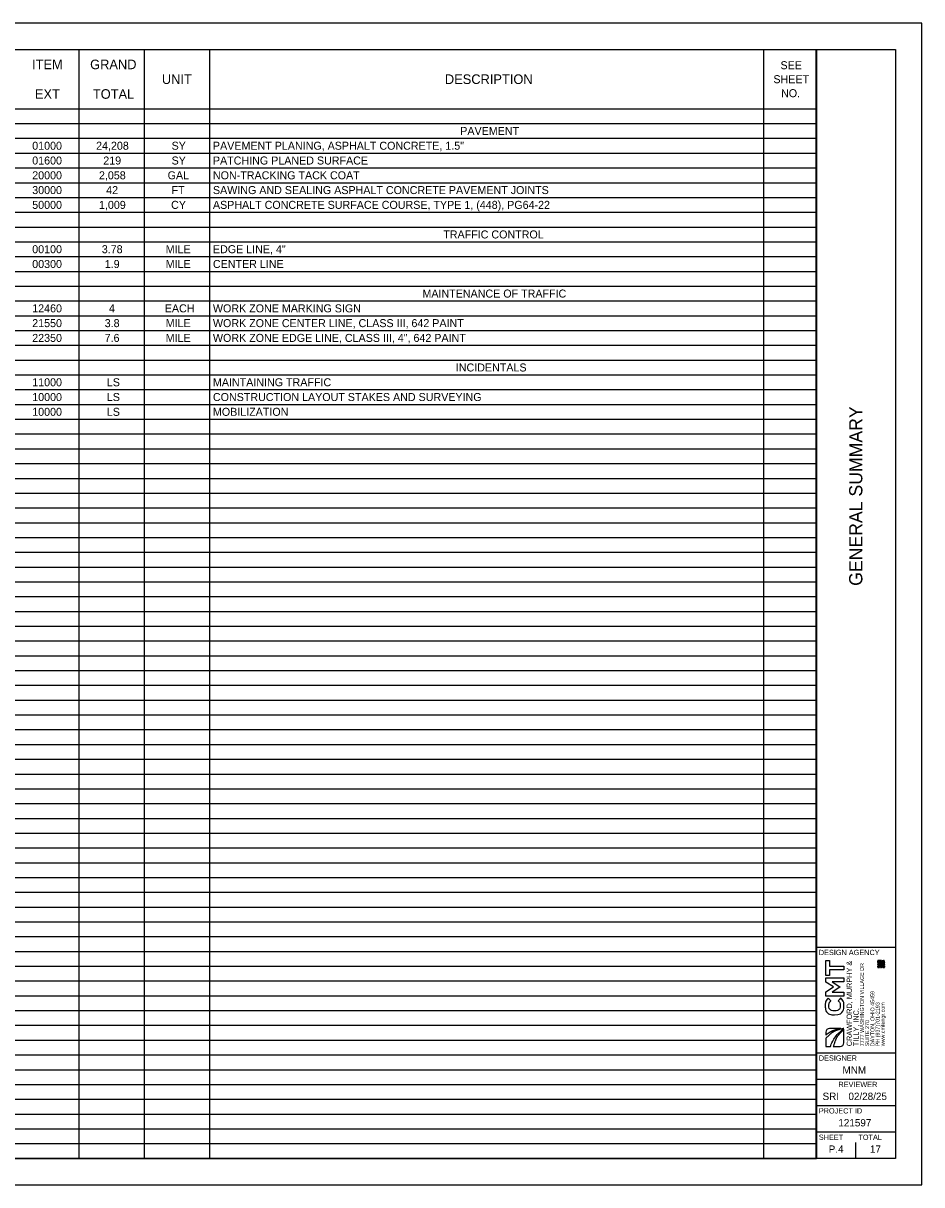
# Model space of a CAD drawing. Extents: x 0 to 34, y 0 to 22.
# Drawn here: x 16.98 to 34, y 0 to 22 of the extents above; entities that cross this region are included whole.
import ezdxf

# ---------------------------------------------------------------- set-up
doc = ezdxf.new("R2010")
doc.units = 0
for name, color, linetype in [('Common-Title block info', 7, 'Continuous'), ('LOGOS', 7, 'Continuous'), ('SH_Border', 7, 'Continuous'), ('SH_Cut_Line', 7, 'Continuous'), ('SH_Data', 7, 'Continuous'), ('SH_Text', 7, 'Continuous')]:
    doc.layers.add(name, color=color, linetype=linetype)

msp = doc.modelspace()

# ---------------------------------------------------------------- linework, layer by layer
at = {"layer": 'Common-Title block info'}
for p, q in [((32.184, 2.889), (32.184, 2.838)), ((32.47, 2.96), (32.254, 2.96)), ((32.525, 2.96), (32.525, 2.96)), ((32.526, 2.688), (32.526, 2.941)), ((32.184, 2.773), (32.184, 2.618)), ((32.184, 2.618), (32.267, 2.618)), ((32.324, 2.618), (32.455, 2.618))]:
    msp.add_line(p, q, dxfattribs=at)
msp.add_lwpolyline([(32.526, 2.941), (32.526, 2.941)], dxfattribs=at)
for centre, start, end in [((32.254, 2.889), 90, 180), ((32.455, 2.688), 270, 360)]:
    msp.add_arc(centre, 0.0708, start, end, dxfattribs=at)
for points, degree in [([(32.525, 2.96), (32.393, 2.934), (32.272, 2.867), (32.184, 2.773)], 2), ([(32.184, 2.838), (32.266, 2.9), (32.365, 2.94), (32.47, 2.96)], 2), ([(32.267, 2.618), (32.267, 2.618), (32.267, 2.618), (32.267, 2.618), (32.323, 2.751), (32.412, 2.869), (32.525, 2.96)], 3), ([(32.526, 2.941), (32.434, 2.857), (32.367, 2.761), (32.324, 2.618)], 2)]:
    msp.add_open_spline(points, degree=degree, dxfattribs=at)
at = {"layer": 'LOGOS'}
for p, q in [((32.182, 3.964), (32.182, 4.248)), ((32.182, 4.248), (32.252, 4.248)), ((32.252, 4.248), (32.252, 4.143)), ((32.252, 3.964), (32.182, 3.964)), ((32.252, 4.143), (32.525, 4.143)), ((32.252, 4.068), (32.252, 3.964)), ((32.525, 4.068), (32.252, 4.068)), ((32.525, 4.143), (32.525, 4.068)), ((32.182, 3.837), (32.182, 3.918)), ((32.182, 3.918), (32.525, 3.918)), ((32.327, 3.747), (32.182, 3.837)), ((32.182, 3.657), (32.327, 3.747)), ((32.525, 3.843), (32.301, 3.843)), ((32.301, 3.843), (32.448, 3.747)), ((32.448, 3.745), (32.303, 3.649)), ((32.448, 3.747), (32.448, 3.745)), ((32.525, 3.918), (32.525, 3.843)), ((32.182, 3.575), (32.182, 3.657)), ((32.525, 3.575), (32.182, 3.575)), ((32.303, 3.649), (32.525, 3.649)), ((32.525, 3.649), (32.525, 3.575))]:
    msp.add_line(p, q, dxfattribs=at)
for points in [[(33.284, 4.243), (33.279, 4.243), (33.279, 4.239), (33.275, 4.239), (33.275, 4.23), (33.265, 4.23), (33.265, 4.234), (33.261, 4.234), (33.261, 4.239), (33.252, 4.239), (33.252, 4.225), (33.256, 4.225), (33.256, 4.221), (33.247, 4.221), (33.247, 4.216), (33.252, 4.216), (33.252, 4.212), (33.238, 4.212), (33.238, 4.221), (33.234, 4.221), (33.234, 4.225), (33.238, 4.225), (33.238, 4.221), (33.247, 4.221), (33.247, 4.225), (33.243, 4.225), (33.243, 4.234), (33.229, 4.234), (33.229, 4.239), (33.225, 4.239), (33.225, 4.243), (33.229, 4.243), (33.229, 4.239), (33.234, 4.239), (33.234, 4.243), (33.238, 4.243), (33.238, 4.248), (33.216, 4.248), (33.216, 4.243), (33.22, 4.243), (33.22, 4.23), (33.229, 4.23), (33.229, 4.225), (33.216, 4.225), (33.216, 4.221), (33.225, 4.221), (33.225, 4.216), (33.234, 4.216), (33.234, 4.212), (33.229, 4.212), (33.229, 4.207), (33.225, 4.207), (33.225, 4.216), (33.22, 4.216), (33.22, 4.212), (33.216, 4.212), (33.216, 4.207), (33.22, 4.207), (33.22, 4.203), (33.211, 4.203), (33.211, 4.212), (33.207, 4.212), (33.207, 4.207), (33.198, 4.207), (33.198, 4.203), (33.193, 4.203), (33.193, 4.207), (33.198, 4.207), (33.198, 4.212), (33.189, 4.212), (33.189, 4.207), (33.184, 4.207), (33.184, 4.212), (33.175, 4.212), (33.175, 4.203), (33.17, 4.203), (33.17, 4.207), (33.166, 4.207), (33.166, 4.198), (33.179, 4.198), (33.179, 4.184), (33.184, 4.184), (33.184, 4.189), (33.189, 4.189), (33.189, 4.193), (33.184, 4.193), (33.184, 4.203), (33.189, 4.203), (33.189, 4.193), (33.193, 4.193), (33.193, 4.198), (33.198, 4.198), (33.198, 4.193), (33.193, 4.193), (33.193, 4.189), (33.202, 4.189), (33.202, 4.203), (33.207, 4.203), (33.207, 4.198), (33.211, 4.198), (33.211, 4.193), (33.216, 4.193), (33.216, 4.198), (33.234, 4.198), (33.234, 4.193), (33.238, 4.193), (33.238, 4.184), (33.234, 4.184), (33.234, 4.18), (33.252, 4.18), (33.252, 4.184), (33.261, 4.184), (33.261, 4.18), (33.252, 4.18), (33.252, 4.171), (33.256, 4.171), (33.256, 4.162), (33.261, 4.162), (33.261, 4.166), (33.265, 4.166), (33.265, 4.175), (33.27, 4.175), (33.27, 4.157), (33.279, 4.157), (33.279, 4.166), (33.275, 4.166), (33.275, 4.171), (33.279, 4.171), (33.279, 4.166), (33.284, 4.166), (33.284, 4.157), (33.279, 4.157), (33.279, 4.153), (33.288, 4.153), (33.288, 4.162), (33.297, 4.162), (33.297, 4.171), (33.293, 4.171), (33.293, 4.166), (33.288, 4.166), (33.288, 4.175), (33.279, 4.175), (33.279, 4.18), (33.284, 4.18), (33.284, 4.184), (33.297, 4.184), (33.297, 4.189), (33.293, 4.189), (33.293, 4.193), (33.297, 4.193), (33.297, 4.212), (33.284, 4.212), (33.284, 4.207), (33.293, 4.207), (33.293, 4.203), (33.284, 4.203), (33.284, 4.198), (33.279, 4.198), (33.279, 4.193), (33.275, 4.193), (33.275, 4.198), (33.27, 4.198), (33.27, 4.207), (33.279, 4.207), (33.279, 4.225), (33.284, 4.225)], [(33.198, 4.248), (33.166, 4.248), (33.166, 4.216), (33.198, 4.216)], [(33.179, 4.184), (33.175, 4.184), (33.175, 4.193), (33.166, 4.193), (33.166, 4.171), (33.17, 4.171), (33.17, 4.166), (33.175, 4.166), (33.175, 4.162), (33.17, 4.162), (33.17, 4.157), (33.179, 4.157), (33.179, 4.162), (33.184, 4.162), (33.184, 4.18), (33.179, 4.18)], [(33.193, 4.243), (33.193, 4.221), (33.17, 4.221), (33.17, 4.243)], [(33.189, 4.239), (33.175, 4.239), (33.175, 4.225), (33.189, 4.225)], [(33.202, 4.189), (33.202, 4.184), (33.193, 4.184), (33.193, 4.18), (33.198, 4.18), (33.198, 4.175), (33.202, 4.175), (33.202, 4.171), (33.198, 4.171), (33.198, 4.166), (33.207, 4.166), (33.207, 4.175), (33.211, 4.175), (33.211, 4.18), (33.207, 4.18), (33.207, 4.189)], [(33.216, 4.243), (33.211, 4.243), (33.211, 4.239), (33.207, 4.239), (33.207, 4.23), (33.202, 4.23), (33.202, 4.225), (33.207, 4.225), (33.207, 4.221), (33.202, 4.221), (33.202, 4.212), (33.207, 4.212), (33.207, 4.216), (33.216, 4.216), (33.216, 4.221), (33.211, 4.221), (33.211, 4.225), (33.216, 4.225)], [(33.211, 4.243), (33.211, 4.248), (33.207, 4.248), (33.207, 4.243)], [(33.211, 4.18), (33.216, 4.18), (33.216, 4.175), (33.22, 4.175), (33.22, 4.157), (33.229, 4.157), (33.229, 4.153), (33.234, 4.153), (33.234, 4.162), (33.225, 4.162), (33.225, 4.166), (33.234, 4.166), (33.234, 4.171), (33.229, 4.171), (33.229, 4.175), (33.225, 4.175), (33.225, 4.18), (33.22, 4.18), (33.22, 4.189), (33.211, 4.189)], [(33.225, 4.189), (33.225, 4.193), (33.22, 4.193), (33.22, 4.189)], [(33.234, 4.184), (33.234, 4.189), (33.225, 4.189), (33.225, 4.18), (33.229, 4.18), (33.229, 4.184)], [(33.265, 4.198), (33.265, 4.193), (33.27, 4.193), (33.27, 4.189), (33.279, 4.189), (33.279, 4.184), (33.275, 4.184), (33.275, 4.18), (33.27, 4.18), (33.27, 4.184), (33.265, 4.184), (33.265, 4.189), (33.261, 4.189), (33.261, 4.193), (33.256, 4.193), (33.256, 4.198), (33.252, 4.198), (33.252, 4.193), (33.247, 4.193), (33.247, 4.189), (33.243, 4.189), (33.243, 4.198), (33.238, 4.198), (33.238, 4.207), (33.252, 4.207), (33.252, 4.203), (33.261, 4.203), (33.261, 4.198)], [(33.252, 4.198), (33.252, 4.203), (33.247, 4.203), (33.247, 4.198)], [(33.265, 4.234), (33.27, 4.234), (33.27, 4.243), (33.265, 4.243), (33.265, 4.248), (33.261, 4.248), (33.261, 4.239), (33.265, 4.239)], [(33.275, 4.225), (33.275, 4.212), (33.261, 4.212), (33.261, 4.225)], [(33.27, 4.221), (33.265, 4.221), (33.265, 4.216), (33.27, 4.216)], [(33.279, 4.243), (33.279, 4.248), (33.275, 4.248), (33.275, 4.243)], [(33.279, 4.203), (33.275, 4.203), (33.275, 4.198), (33.279, 4.198)], [(33.284, 4.207), (33.279, 4.207), (33.279, 4.203), (33.284, 4.203)], [(33.288, 4.243), (33.288, 4.248), (33.284, 4.248), (33.284, 4.243)], [(33.284, 4.225), (33.284, 4.221), (33.288, 4.221), (33.288, 4.225)], [(33.297, 4.239), (33.297, 4.243), (33.288, 4.243), (33.288, 4.239)], [(33.293, 4.225), (33.293, 4.234), (33.288, 4.234), (33.288, 4.225)], [(33.288, 4.221), (33.288, 4.216), (33.297, 4.216), (33.297, 4.225), (33.293, 4.225), (33.293, 4.221)], [(33.198, 4.148), (33.166, 4.148), (33.166, 4.117), (33.198, 4.117)], [(33.175, 4.18), (33.175, 4.175), (33.17, 4.175), (33.17, 4.18)], [(33.193, 4.144), (33.193, 4.121), (33.17, 4.121), (33.17, 4.144)], [(33.189, 4.126), (33.189, 4.139), (33.175, 4.139), (33.175, 4.126)], [(33.189, 4.153), (33.189, 4.157), (33.184, 4.157), (33.184, 4.153)], [(33.193, 4.18), (33.189, 4.18), (33.189, 4.175), (33.193, 4.175)], [(33.193, 4.175), (33.193, 4.171), (33.198, 4.171), (33.198, 4.175)], [(33.207, 4.166), (33.207, 4.162), (33.202, 4.162), (33.202, 4.157), (33.193, 4.157), (33.193, 4.153), (33.202, 4.153), (33.202, 4.144), (33.207, 4.144), (33.207, 4.157), (33.211, 4.157), (33.211, 4.162), (33.216, 4.162), (33.216, 4.166)], [(33.198, 4.166), (33.193, 4.166), (33.193, 4.162), (33.198, 4.162)], [(33.211, 4.135), (33.202, 4.135), (33.202, 4.126), (33.211, 4.126)], [(33.229, 4.153), (33.22, 4.153), (33.22, 4.139), (33.216, 4.139), (33.216, 4.148), (33.211, 4.148), (33.211, 4.135), (33.22, 4.135), (33.22, 4.126), (33.225, 4.126), (33.225, 4.13), (33.238, 4.13), (33.238, 4.135), (33.243, 4.135), (33.243, 4.13), (33.252, 4.13), (33.252, 4.126), (33.256, 4.126), (33.256, 4.121), (33.261, 4.121), (33.261, 4.13), (33.256, 4.13), (33.256, 4.139), (33.252, 4.139), (33.252, 4.148), (33.256, 4.148), (33.256, 4.144), (33.261, 4.144), (33.261, 4.153), (33.27, 4.153), (33.27, 4.157), (33.256, 4.157), (33.256, 4.153), (33.252, 4.153), (33.252, 4.157), (33.247, 4.157), (33.247, 4.153), (33.243, 4.153), (33.243, 4.157), (33.238, 4.157), (33.238, 4.153), (33.234, 4.153), (33.234, 4.148), (33.238, 4.148), (33.238, 4.144), (33.243, 4.144), (33.243, 4.148), (33.247, 4.148), (33.247, 4.139), (33.234, 4.139), (33.234, 4.135), (33.225, 4.135), (33.225, 4.139), (33.234, 4.139), (33.234, 4.148), (33.229, 4.148), (33.229, 4.144), (33.225, 4.144), (33.225, 4.148), (33.229, 4.148)], [(33.211, 4.126), (33.211, 4.117), (33.216, 4.117), (33.216, 4.126)], [(33.234, 4.18), (33.229, 4.18), (33.229, 4.175), (33.234, 4.175)], [(33.234, 4.121), (33.234, 4.126), (33.229, 4.126), (33.229, 4.121)], [(33.234, 4.171), (33.243, 4.171), (33.243, 4.166), (33.252, 4.166), (33.252, 4.171), (33.247, 4.171), (33.247, 4.175), (33.234, 4.175)], [(33.238, 4.121), (33.234, 4.121), (33.234, 4.117), (33.238, 4.117)], [(33.243, 4.166), (33.238, 4.166), (33.238, 4.162), (33.243, 4.162)], [(33.238, 4.13), (33.238, 4.121), (33.243, 4.121), (33.243, 4.13)], [(33.252, 4.117), (33.252, 4.121), (33.247, 4.121), (33.247, 4.117)], [(33.297, 4.148), (33.265, 4.148), (33.265, 4.117), (33.297, 4.117)], [(33.293, 4.144), (33.293, 4.121), (33.27, 4.121), (33.27, 4.144)], [(33.288, 4.139), (33.275, 4.139), (33.275, 4.126), (33.288, 4.126)], [(33.288, 4.175), (33.297, 4.175), (33.297, 4.18), (33.288, 4.18)]]:
    msp.add_lwpolyline(points, close=True, dxfattribs=at)
msp.add_open_spline([(32.35, 3.217), (32.35, 3.217), (32.349, 3.217), (32.349, 3.217), (32.251, 3.217), (32.172, 3.29), (32.172, 3.396), (32.172, 3.46), (32.193, 3.499), (32.224, 3.531), (32.224, 3.531), (32.28, 3.483), (32.28, 3.483), (32.256, 3.456), (32.241, 3.43), (32.241, 3.395), (32.241, 3.337), (32.289, 3.296), (32.348, 3.296), (32.348, 3.296), (32.349, 3.296), (32.349, 3.296), (32.407, 3.296), (32.456, 3.337), (32.456, 3.395), (32.456, 3.434), (32.441, 3.458), (32.416, 3.485), (32.416, 3.485), (32.465, 3.533), (32.465, 3.533), (32.502, 3.498), (32.526, 3.459), (32.526, 3.393), (32.526, 3.292), (32.448, 3.217), (32.35, 3.217)], degree=3, dxfattribs=at)
at = {"layer": 'SH_Border'}
for p, q in [((32, 0.5), (32, 21.5)), ((32, 4.5), (33.5, 4.5)), ((32, 2.5), (33.5, 2.5)), ((32, 2), (33.5, 2)), ((32, 1.5), (33.5, 1.5)), ((32, 1), (33.5, 1))]:
    msp.add_line(p, q, dxfattribs=at)
msp.add_lwpolyline([(1.5, 21.5), (33.5, 21.5), (33.5, 0.5), (1.5, 0.5)], close=True, dxfattribs=at)
at = {"layer": 'SH_Cut_Line'}
msp.add_lwpolyline([(0, 0), (34, 0), (34, 22), (0, 22)], close=True, dxfattribs=at)
at = {"layer": 'SH_Data'}
for p, q in [((32.75, 3.5), (32.75, 3.5)), ((32.375, 0.675), (32.375, 0.675)), ((32.75, 0.5), (32.75, 0.8))]:
    msp.add_line(p, q, dxfattribs=at)
at = {"layer": 'SH_Text'}
for p, q in [((1.5, 21.5), (32.004, 21.5)), ((18.036, 21.5), (18.036, 0.5)), ((19.272, 21.5), (19.272, 0.5)), ((20.507, 21.5), (20.507, 0.5)), ((30.999, 21.5), (30.999, 0.5)), ((32.004, 21.5), (32.004, 0.5)), ((1.5, 20.38), (32.004, 20.38)), ((1.5, 20.1), (32.004, 20.1)), ((1.5, 19.82), (32.004, 19.82)), ((1.5, 19.54), (32.004, 19.54)), ((1.5, 19.26), (32.004, 19.26)), ((1.5, 18.98), (32.004, 18.98)), ((1.5, 18.7), (32.004, 18.7)), ((1.5, 18.42), (32.004, 18.42)), ((1.5, 18.14), (32.004, 18.14)), ((1.5, 17.86), (32.004, 17.86)), ((1.5, 17.58), (32.004, 17.58)), ((1.5, 17.3), (32.004, 17.3)), ((1.5, 17.02), (32.004, 17.02)), ((1.5, 16.74), (32.004, 16.74)), ((1.5, 16.46), (32.004, 16.46)), ((1.5, 16.18), (32.004, 16.18)), ((1.5, 15.9), (32.004, 15.9)), ((1.5, 15.62), (32.004, 15.62)), ((1.5, 15.34), (32.004, 15.34)), ((1.5, 15.06), (32.004, 15.06)), ((1.5, 14.78), (32.004, 14.78)), ((1.5, 14.5), (32.004, 14.5)), ((1.5, 14.22), (32.004, 14.22)), ((1.5, 13.94), (32.004, 13.94)), ((1.5, 13.66), (32.004, 13.66)), ((1.5, 13.38), (32.004, 13.38)), ((1.5, 13.1), (32.004, 13.1)), ((1.5, 12.82), (32.004, 12.82)), ((1.5, 12.54), (32.004, 12.54)), ((1.5, 12.26), (32.004, 12.26)), ((1.5, 11.98), (32.004, 11.98)), ((1.5, 11.7), (32.004, 11.7)), ((1.5, 11.42), (32.004, 11.42)), ((1.5, 11.14), (32.004, 11.14)), ((1.5, 10.86), (32.004, 10.86)), ((1.5, 10.58), (32.004, 10.58)), ((1.5, 10.3), (32.004, 10.3)), ((1.5, 10.02), (32.004, 10.02)), ((1.5, 9.74), (32.004, 9.74)), ((1.5, 9.46), (32.004, 9.46)), ((1.5, 9.18), (32.004, 9.18)), ((1.5, 8.9), (32.004, 8.9)), ((1.5, 8.62), (32.004, 8.62)), ((1.5, 8.34), (32.004, 8.34)), ((1.5, 8.06), (32.004, 8.06)), ((1.5, 7.78), (32.004, 7.78)), ((1.5, 7.5), (32.004, 7.5)), ((1.5, 7.22), (32.004, 7.22)), ((1.5, 6.94), (32.004, 6.94)), ((1.5, 6.66), (32.004, 6.66)), ((1.5, 6.38), (32.004, 6.38)), ((1.5, 6.1), (32.004, 6.1)), ((1.5, 5.82), (32.004, 5.82)), ((1.5, 5.54), (32.004, 5.54)), ((1.5, 5.26), (32.004, 5.26)), ((1.5, 4.98), (32.004, 4.98)), ((1.5, 4.7), (32.004, 4.7)), ((1.5, 4.42), (32.004, 4.42)), ((1.5, 4.14), (32.004, 4.14)), ((1.5, 3.86), (32.004, 3.86)), ((1.5, 3.58), (32.004, 3.58)), ((1.5, 3.3), (32.004, 3.3)), ((1.5, 3.02), (32.004, 3.02)), ((1.5, 2.74), (32.004, 2.74)), ((1.5, 2.46), (32.004, 2.46)), ((1.5, 2.18), (32.004, 2.18)), ((1.5, 1.9), (32.004, 1.9)), ((1.5, 1.62), (32.004, 1.62)), ((1.5, 1.34), (32.004, 1.34)), ((1.5, 1.06), (32.004, 1.06)), ((1.5, 0.78), (32.004, 0.78)), ((1.5, 0.5), (32.004, 0.5))]:
    msp.add_line(p, q, dxfattribs=at)

# ---------------------------------------------------------------- texts
at = {"layer": 'LOGOS'}
for s, height, p in [('CRAWFORD, MURPHY &', 0.1, (32.677, 2.624)), ('7777 WASHINGTON VILLAGE DR', 0.07331, (32.904, 2.624)), ('DAYTON, OHIO 45459', 0.07331, (33.102, 2.624)), ('TILLY, INC.', 0.1, (32.806, 2.624)), ('PH (937)701-2193', 0.07331, (33.2, 2.624)), ('www.cmtengr.com', 0.07331, (33.299, 2.624)), ('SUITE 270', 0.0733, (33.003, 2.624))]:
    msp.add_text(s, height=height, rotation=90, dxfattribs=at).set_placement(p)
at = {"layer": 'SH_Data'}
msp.add_text('GENERAL SUMMARY', height=0.25, rotation=90, dxfattribs=at).set_placement((32.875, 11.344))
for s, height, p in [('DESIGN AGENCY', 0.1, (32.05, 4.35)), ('DESIGNER', 0.1, (32.05, 2.35)), ('MNM', 0.14, (32.499, 2.105)), ('REVIEWER', 0.1, (32.422, 1.85)), ('SRI', 0.14, (32.121, 1.605)), ('02/28/25', 0.14, (32.611, 1.605)), ('PROJECT ID', 0.1, (32.05, 1.35)), ('121597', 0.14, (32.42, 1.105)), ('SHEET', 0.1, (32.05, 0.85)), ('TOTAL', 0.1, (32.8, 0.85)), ('P.4', 0.14, (32.237, 0.605)), ('17', 0.14, (33.018, 0.605))]:
    msp.add_text(s, height=height, dxfattribs=at).set_placement(p)
at = {"layer": 'SH_Text'}
for s, height, p in [('ITEM', 0.1818, (17.147, 21.129)), ('GRAND', 0.1818, (18.247, 21.129)), ('SEE ', 0.1515, (31.324, 21.129)), ('UNIT', 0.1818, (19.606, 20.849)), ('DESCRIPTION', 0.18184, (24.967, 20.849)), ('SHEET ', 0.1515, (31.19, 20.864)), ('EXT', 0.1818, (17.201, 20.569)), ('TOTAL', 0.1818, (18.299, 20.569)), ('NO.', 0.1515, (31.335, 20.599)), ('PAVEMENT', 0.1515, (25.258, 19.884)), ('01000', 0.1515, (17.15, 19.604)), ('24,208', 0.1515, (18.36, 19.604)), ('SY', 0.1515, (19.79, 19.604)), ('PAVEMENT PLANING, ASPHALT CONCRETE, 1.5"', 0.15153, (20.573, 19.604)), ('01600', 0.1515, (17.15, 19.324)), ('219', 0.1515, (18.496, 19.324)), ('SY', 0.1515, (19.79, 19.324)), ('PATCHING PLANED SURFACE', 0.15153, (20.573, 19.324)), ('20000', 0.1515, (17.15, 19.044)), ('2,058', 0.1515, (18.414, 19.044)), ('GAL', 0.1515, (19.715, 19.044)), ('NON-TRACKING TACK COAT', 0.15153, (20.573, 19.044)), ('30000', 0.1515, (17.15, 18.764)), ('42', 0.1515, (18.551, 18.764)), ('FT', 0.1515, (19.789, 18.764)), ('SAWING AND SEALING ASPHALT CONCRETE PAVEMENT JOINTS', 0.15153, (20.573, 18.764)), ('50000', 0.1515, (17.15, 18.484)), ('1,009', 0.1515, (18.415, 18.484)), ('CY', 0.1515, (19.781, 18.484)), ('ASPHALT CONCRETE SURFACE COURSE, TYPE 1, (448), PG64-22', 0.15153, (20.573, 18.484)), ('TRAFFIC CONTROL', 0.15153, (24.936, 17.924)), ('00100', 0.1515, (17.15, 17.644)), ('3.78', 0.1515, (18.468, 17.644)), ('MILE', 0.1515, (19.679, 17.644)), ('EDGE LINE, 4"', 0.15153, (20.573, 17.644)), ('00300', 0.1515, (17.15, 17.364)), ('1.9', 0.1515, (18.524, 17.364)), ('MILE', 0.1515, (19.679, 17.364)), ('CENTER LINE', 0.15153, (20.573, 17.364)), ('MAINTENANCE OF TRAFFIC', 0.15153, (24.542, 16.804)), ('12460', 0.1515, (17.15, 16.524)), ('4', 0.152, (18.603, 16.524)), ('EACH', 0.1515, (19.661, 16.524)), ('WORK ZONE MARKING SIGN', 0.15153, (20.573, 16.524)), ('21550', 0.1515, (17.15, 16.244)), ('3.8', 0.1515, (18.523, 16.244)), ('MILE', 0.1515, (19.679, 16.244)), ('WORK ZONE CENTER LINE, CLASS III, 642 PAINT', 0.15153, (20.573, 16.244)), ('22350', 0.1515, (17.15, 15.964)), ('7.6', 0.1515, (18.522, 15.964)), ('MILE', 0.1515, (19.679, 15.964)), ('WORK ZONE EDGE LINE, CLASS III, 4", 642 PAINT', 0.15153, (20.573, 15.964)), ('INCIDENTALS', 0.15153, (25.174, 15.404)), ('11000', 0.1515, (17.15, 15.124)), ('LS', 0.1515, (18.564, 15.124)), ('MAINTAINING TRAFFIC', 0.15153, (20.573, 15.124)), ('10000', 0.1515, (17.15, 14.844)), ('LS', 0.1515, (18.564, 14.844)), ('CONSTRUCTION LAYOUT STAKES AND SURVEYING', 0.15153, (20.573, 14.844)), ('10000', 0.1515, (17.15, 14.564)), ('LS', 0.1515, (18.564, 14.564)), ('MOBILIZATION', 0.15153, (20.573, 14.564))]:
    msp.add_text(s, height=height, dxfattribs=at).set_placement(p)

doc.saveas('drawing.dxf')
